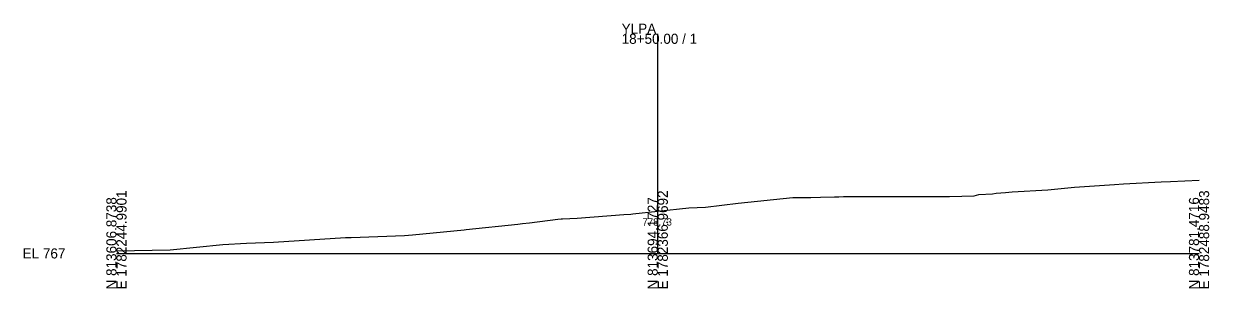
# Model space of a CAD drawing. Extents: x -76 to 1303, y -10 to 9544.
# Drawn here: x -25.7 to 302.8, y 8490.3 to 8563.8 of the extents above; entities that cross this region are included whole.
import ezdxf

# ---------------------------------------------------------------- set-up
doc = ezdxf.new("R2010")
doc.units = 0
for name, color, linetype in [('Exist Cross Section Cell', 7, 'Continuous'), ('Exist XS Center Line Elevation Label', 7, 'Continuous'), ('Exist XS Ground Line', 7, 'Continuous')]:
    doc.layers.add(name, color=color, linetype=linetype)

msp = doc.modelspace()

# ---------------------------------------------------------------- linework, layer by layer
at = {"layer": 'Exist Cross Section Cell'}
for p, q in [((150, 8500), (150, 8560.98)), ((0, 8500), (150, 8500)), ((150, 8500), (300, 8500))]:
    msp.add_line(p, q, dxfattribs=at)
at = {"layer": 'Exist XS Ground Line'}
for p, q in [((265.5, 8518.36), (276.57, 8519.17)), ((276.57, 8519.17), (279.05, 8519.31)), ((279.05, 8519.31), (289.53, 8519.9)), ((289.53, 8519.9), (292.09, 8519.95)), ((292.09, 8519.95), (300, 8520.33)), ((192.41, 8515.54), (195.11, 8515.58)), ((195.11, 8515.58), (199, 8515.72)), ((199, 8515.72), (200.21, 8515.75)), ((200.21, 8515.75), (201.47, 8515.77)), ((201.47, 8515.77), (207.93, 8515.79)), ((207.93, 8515.79), (212.54, 8515.83)), ((212.54, 8515.83), (215.7, 8515.82)), ((215.7, 8515.82), (220.05, 8515.8)), ((220.05, 8515.8), (225.88, 8515.8)), ((225.88, 8515.8), (230.89, 8515.82)), ((230.89, 8515.82), (237.66, 8515.99)), ((237.66, 8515.99), (239, 8516.35)), ((239, 8516.35), (242.75, 8516.58)), ((242.75, 8516.58), (243.77, 8516.68)), ((243.77, 8516.68), (246.4, 8516.88)), ((246.4, 8516.88), (248.19, 8517.07)), ((248.19, 8517.07), (258.13, 8517.69)), ((258.13, 8517.69), (265.5, 8518.36)), ((150, 8511.73), (158.59, 8512.67)), ((158.59, 8512.67), (163.24, 8512.82)), ((163.24, 8512.82), (172.31, 8513.92)), ((172.31, 8513.92), (187.45, 8515.48)), ((187.45, 8515.48), (192.41, 8515.54)), ((114.48, 8508.47), (122.29, 8509.5)), ((122.29, 8509.5), (123.2, 8509.62)), ((123.2, 8509.62), (123.65, 8509.64)), ((123.65, 8509.64), (127.63, 8509.8)), ((127.63, 8509.8), (140.64, 8510.78)), ((140.64, 8510.78), (142.55, 8510.9)), ((142.55, 8510.9), (143.13, 8510.97)), ((143.13, 8510.97), (150, 8511.73)), ((82.05, 8505.17), (96.34, 8506.54)), ((96.34, 8506.54), (96.91, 8506.6)), ((96.91, 8506.6), (111.26, 8508.16)), ((111.26, 8508.16), (112.56, 8508.29)), ((112.56, 8508.29), (114.48, 8508.47)), ((14.85, 8500.95), (29.48, 8502.49)), ((29.48, 8502.49), (36.02, 8502.84)), ((36.02, 8502.84), (43.55, 8503.12)), ((43.55, 8503.12), (63.44, 8504.39)), ((63.44, 8504.39), (65.03, 8504.42)), ((65.03, 8504.42), (79.8, 8504.95)), ((79.8, 8504.95), (82.05, 8505.17)), ((0, 8500.74), (14.85, 8500.95))]:
    msp.add_line(p, q, dxfattribs=at)

# ---------------------------------------------------------------- texts
at = {"layer": 'Exist Cross Section Cell'}
for s, p in [('YLPA', (140, 8560.98)), ('18+50.00 / 1', (140, 8558.18)), ('EL 767', (-26, 8498.6))]:
    msp.add_text(s, height=2.8, dxfattribs=at).set_placement(p)
for s, p in [('E 1782244.9901', (2.8, 8490)), ('E 1782366.9692', (152.8, 8490)), ('E 1782488.9483', (302.8, 8490)), ('N 813606.8738', (0, 8490)), ('N 813694.1727', (150, 8490)), ('N 813781.4716', (300, 8490))]:
    msp.add_text(s, height=2.8, rotation=90, dxfattribs=at).set_placement(p)
at = {"layer": 'Exist XS Center Line Elevation Label'}
msp.add_text('778.73', height=2, dxfattribs=at).set_placement((145.75, 8507.73))

doc.saveas('drawing.dxf')
